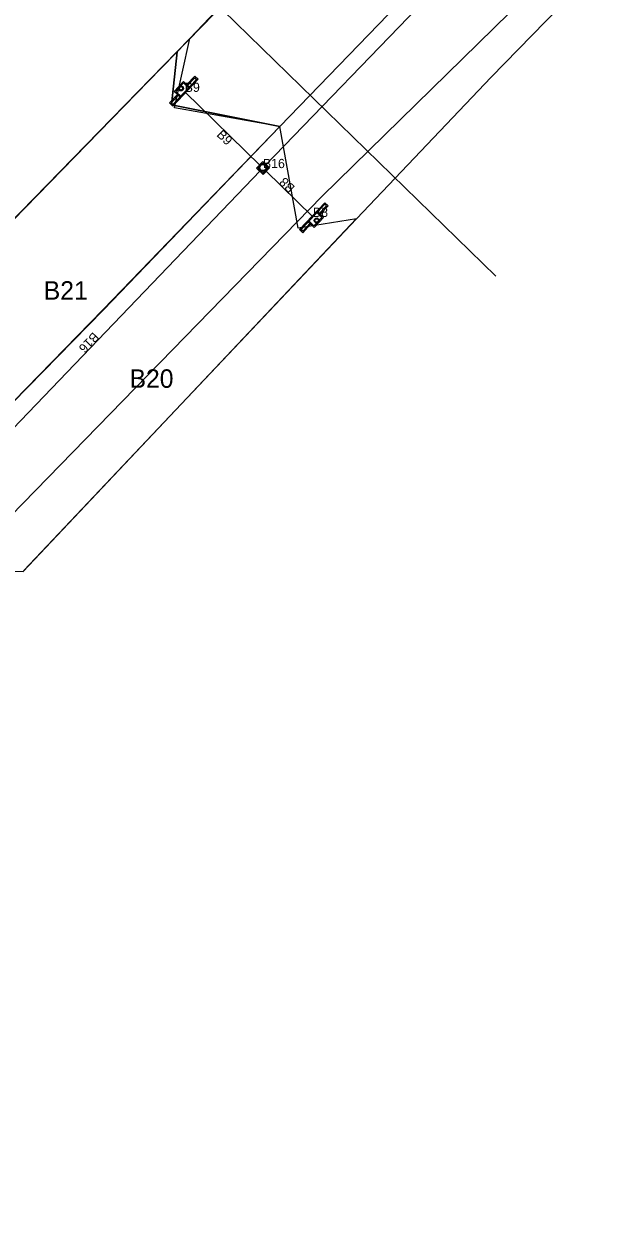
# Model space of a CAD drawing. Extents: x 2253035 to 2279930, y 13774972 to 13793443.
# Drawn here: x 2255823 to 2256071, y 13791353 to 13791870 of the extents above; entities that cross this region are included whole.
import ezdxf

# ---------------------------------------------------------------- set-up
doc = ezdxf.new("R2010")
doc.units = 0
for name, color, linetype in [('E_Utility_ATT_Fiber', 7, 'Continuous'), ('E_Utility_ATT_Xbox', 7, 'Continuous'), ('E_Utility_Electric_Power Pole_PP_Description', 7, 'Continuous'), ('E_Utility_Fiber Optic_Fiber Optic Cable_FOC', 7, 'Continuous'), ('E_Utility_Gas_Gas Line_GL_Description', 7, 'Continuous'), ('E_Utility_Gas_Gas Line_GL_Elevation', 7, 'Continuous'), ('E_Utility_Water_Water Line_WL_Elevation', 7, 'Continuous'), ('E_Utility_Water_Water Valve_WV_Elevation', 7, 'Continuous')]:
    doc.layers.add(name, color=color, linetype=linetype)

msp = doc.modelspace()

# ---------------------------------------------------------------- linework, layer by layer
at = {"layer": 'E_Utility_ATT_Fiber'}
for p, q in [((2255889.49, 13791857.83), (2255951.39, 13791922.73)), ((2255951.39, 13791922.73), (2255889.49, 13791857.83)), ((2255882.44, 13791850.6), (2255889.49, 13791857.83)), ((2255889.49, 13791857.83), (2255882.44, 13791850.6)), ((2255887.08, 13791834.88), (2255889.49, 13791857.83)), ((2255889.49, 13791857.83), (2255887.08, 13791834.88)), ((2255818.49, 13791785.03), (2255882.44, 13791850.6)), ((2255882.44, 13791850.6), (2255818.49, 13791785.03)), ((2255934.04, 13791825.57), (2255887.08, 13791834.88)), ((2255887.08, 13791834.88), (2255934.04, 13791825.57)), ((2255934.04, 13791825.57), (2255857.62, 13791746.14)), ((2255857.62, 13791746.14), (2255934.04, 13791825.57)), ((2255941.93, 13791781.43), (2255934.04, 13791825.57)), ((2255823.16, 13791633.32), (2255967.21, 13791785.59)), ((2255967.21, 13791785.59), (2255941.93, 13791781.43)), ((2255857.62, 13791746.14), (2255784.86, 13791671.82)), ((2255784.86, 13791671.82), (2255857.62, 13791746.14))]:
    msp.add_line(p, q, dxfattribs=at)
msp.add_lwpolyline([(2256171.13, 13792017.36), (2256192.1, 13792017.74), (2256119.93, 13791943.73), (2256025.48, 13791846.89), (2255967.21, 13791785.59), (2255941.93, 13791781.43), (2255934.04, 13791825.57), (2255989.41, 13791882.95), (2256156.41, 13792054.2)], close=True, dxfattribs=at)
for points in [[(2255934.04, 13791825.57), (2255989.41, 13791882.95), (2256156.41, 13792054.2)], [(2255882.44, 13791850.6), (2255882.44, 13791850.6)], [(2255802.53, 13791633.01), (2255822.82, 13791632.96), (2255967.11, 13791785.49)]]:
    msp.add_lwpolyline(points, dxfattribs=at)
at = {"layer": 'E_Utility_ATT_Xbox'}
for p, q in [((2255893.45, 13791843.31), (2255893.45, 13791843.31)), ((2255890.01, 13791839.68), (2255890.01, 13791839.68)), ((2255890.64, 13791842.53), (2255890.64, 13791842.53)), ((2255891.73, 13791841.5), (2255891.73, 13791841.5)), ((2255892.82, 13791840.47), (2255892.82, 13791840.47)), ((2255925.58, 13791808.52), (2255925.58, 13791808.52)), ((2255926.67, 13791807.49), (2255926.67, 13791807.49)), ((2255927.7, 13791808.58), (2255927.7, 13791808.58)), ((2255925.63, 13791806.4), (2255925.63, 13791806.4)), ((2255927.75, 13791806.46), (2255927.75, 13791806.46)), ((2255948.34, 13791786.38), (2255948.34, 13791786.38)), ((2255951.14, 13791787.16), (2255951.14, 13791787.16)), ((2255947.71, 13791783.53), (2255947.71, 13791783.53)), ((2255949.43, 13791785.35), (2255949.43, 13791785.35)), ((2255950.51, 13791784.32), (2255950.51, 13791784.32))]:
    msp.add_line(p, q, dxfattribs=at)
at = {"layer": 'E_Utility_Electric_Power Pole_PP_Description'}
msp.add_line((2255889.33, 13791895.46), (2256027.49, 13791760.72), dxfattribs=at)
at = {"layer": 'E_Utility_Fiber Optic_Fiber Optic Cable_FOC'}
for p, q in [((2255887.67, 13791835.02), (2255897.97, 13791845.91)), ((2255887.69, 13791834.31), (2255898.68, 13791845.93)), ((2255888.22, 13791840.69), (2255892.34, 13791845.05)), ((2255888.92, 13791840.71), (2255892.36, 13791844.34)), ((2255892.34, 13791845.05), (2255893.79, 13791843.68)), ((2255892.36, 13791844.34), (2255894.9, 13791841.94)), ((2255893.79, 13791843.68), (2255897.23, 13791847.31)), ((2255893.79, 13791843.68), (2255895.24, 13791842.3)), ((2255893.81, 13791842.97), (2255897.25, 13791846.6)), ((2255897.23, 13791847.31), (2255898.68, 13791845.93)), ((2255897.25, 13791846.6), (2255898.34, 13791845.57)), ((2255886.23, 13791835.68), (2255889.67, 13791839.32)), ((2255886.94, 13791835.7), (2255890.38, 13791839.34)), ((2255888.22, 13791840.69), (2255889.67, 13791839.32)), ((2255888.92, 13791840.71), (2255891.46, 13791838.31)), ((2255889.67, 13791839.32), (2255891.12, 13791837.94)), ((2255886.23, 13791835.68), (2255887.69, 13791834.31)), ((2255886.94, 13791835.7), (2255888.03, 13791834.67)), ((2255923.84, 13791807.41), (2255926.59, 13791810.32)), ((2255926.74, 13791804.66), (2255923.84, 13791807.41)), ((2255924.54, 13791807.43), (2255926.61, 13791809.61)), ((2255926.72, 13791805.37), (2255924.54, 13791807.43)), ((2255926.59, 13791810.32), (2255929.49, 13791807.57)), ((2255926.61, 13791809.61), (2255928.79, 13791807.55)), ((2255928.79, 13791807.55), (2255926.72, 13791805.37)), ((2255929.49, 13791807.57), (2255926.74, 13791804.66)), ((2255953.47, 13791792.53), (2255942.47, 13791780.91)), ((2255953.49, 13791791.83), (2255943.18, 13791780.93)), ((2255954.22, 13791791.14), (2255953.13, 13791792.17)), ((2255954.92, 13791791.16), (2255953.47, 13791792.53)), ((2255952.23, 13791786.13), (2255948.8, 13791782.5)), ((2255952.94, 13791786.15), (2255948.82, 13791781.79)), ((2255952.23, 13791786.13), (2255949.69, 13791788.54)), ((2255951.49, 13791787.53), (2255950.03, 13791788.9)), ((2255954.22, 13791791.14), (2255950.78, 13791787.51)), ((2255954.92, 13791791.16), (2255951.49, 13791787.53)), ((2255952.94, 13791786.15), (2255951.49, 13791787.53)), ((2255943.93, 13791779.53), (2255942.47, 13791780.91)), ((2255943.91, 13791780.24), (2255942.82, 13791781.27)), ((2255947.34, 13791783.87), (2255943.91, 13791780.24)), ((2255947.36, 13791783.17), (2255943.93, 13791779.53)), ((2255947.36, 13791783.17), (2255945.91, 13791784.54)), ((2255948.8, 13791782.5), (2255946.25, 13791784.9)), ((2255948.82, 13791781.79), (2255947.36, 13791783.17))]:
    msp.add_line(p, q, dxfattribs=at)
for centre, radius in [((2255891.19, 13791842.01), 1.08), ((2255891.19, 13791842.01), 0.75), ((2255926.66, 13791807.72), 1.67), ((2255926.66, 13791807.72), 1.33), ((2255949.97, 13791784.83), 1.08), ((2255949.97, 13791784.83), 0.75)]:
    msp.add_circle(centre, radius, dxfattribs=at)
at = {"layer": 'E_Utility_Gas_Gas Line_GL_Description'}
for p, q in [((2256154.01, 13792043.13), (2255927.7, 13791808.58)), ((2255892.82, 13791840.47), (2255925.58, 13791808.52)), ((2255925.63, 13791806.4), (2255786.56, 13791661.57)), ((2255948.34, 13791786.38), (2255927.75, 13791806.46))]:
    msp.add_line(p, q, dxfattribs=at)
at = {"layer": 'E_Utility_Water_Water Line_WL_Elevation'}
msp.add_lwpolyline([(2255552.69, 13792209.6), (2255414.64, 13792056.03), (2255343.69, 13791984.84), (2255605.99, 13791701.86), (2255609.85, 13791705.81), (2255620.44, 13791716), (2255687.16, 13791650.79), (2255732.69, 13791697.37), (2255738.56, 13791691.61), (2255743.07, 13791696.22), (2255737.22, 13791701.96), (2255882.44, 13791850.6), (2255952.2, 13791922.14), (2256017.05, 13791988.64), (2256050.99, 13792008.43), (2256083.27, 13792042.75), (2256102.42, 13792056.55), (2256121.52, 13792085.4), (2256170.83, 13792144.18)], dxfattribs=at)
msp.add_lwpolyline([(2255888.46, 13791833.54), (2255895.06, 13791863.54), (2255737.22, 13791701.96), (2255743.07, 13791696.22), (2255738.56, 13791691.61), (2255732.69, 13791697.37), (2255687.16, 13791650.79), (2255620.44, 13791716), (2255529.19, 13791619.16), (2255654.52, 13791602.43), (2255648.22, 13791595.97), (2255641.92, 13791570.19), (2255680.31, 13791564.67), (2255857.51, 13791746.27), (2255934.02, 13791825.55)], close=True, dxfattribs=at)
at = {"layer": 'E_Utility_Water_Water Valve_WV_Elevation'}
msp.add_lwpolyline([(2255390.98, 13791330.06), (2255459.85, 13791397.22), (2255383.32, 13791459.9), (2255493.57, 13791567.11), (2255547.29, 13791645.62), (2255605.99, 13791701.86), (2255343.69, 13791984.84), (2255414.64, 13792056.03), (2255552.69, 13792209.6), (2256003.03, 13792697.26), (2256274.85, 13792371.04), (2256429.6, 13792200.7), (2256502.73, 13792117.35), (2256310.07, 13791948.12), (2256237.1, 13792031.76), (2256159.74, 13792001.95), (2256121.45, 13791961.04), (2255952.32, 13791795.31), (2255623, 13791457.45), (2255517, 13791344.43)], dxfattribs=at)

# ---------------------------------------------------------------- texts
at = {"layer": 'E_Utility_Gas_Gas Line_GL_Elevation'}
for s, height, p in [('B9', 4, (2255892.82, 13791840.47)), ('B16', 4, (2255926.67, 13791807.49)), ('B8', 4, (2255948.34, 13791786.38)), ('B21', 8, (2255831.79, 13791750.54)), ('B20', 8, (2255868.93, 13791712.4))]:
    msp.add_text(s, height=height, dxfattribs=at).set_placement(p)
for s, rotation, p in [('B9', 315.7165, (2255906.4, 13791821.63)), ('B8', 135.7052, (2255940.84, 13791799.28)), ('B16', 226.162, (2255853.21, 13791736.75))]:
    msp.add_text(s, height=4, rotation=rotation, dxfattribs=at).set_placement(p)

doc.saveas('drawing.dxf')
